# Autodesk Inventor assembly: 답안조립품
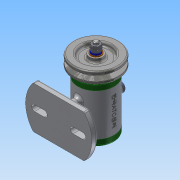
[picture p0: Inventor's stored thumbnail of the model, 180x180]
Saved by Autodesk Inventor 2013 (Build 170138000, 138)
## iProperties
Created: 2017-12
Part Number: 답안조립품
Document SubType Name: Assembly
Designer: Administrator
Author: Administrator
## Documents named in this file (14)
- C:\Users\Administrator\Desktop\471208V1011\답안조립품.iam
- C:\Users\Administrator\Desktop\471208V1011\본체.ipt
- C:\Users\Administrator\Desktop\471208V1011\V벨트풀리.ipt
- C:\Users\Administrator\Desktop\471208V1011\고무캡.ipt
- C:\Users\Administrator\Desktop\471208V1011\너트 M 8.ipt
- C:\Users\Administrator\Desktop\471208V1011\뒤커버.ipt
- C:\Users\Administrator\Desktop\471208V1011\베어링 15 x 32 x 9.ipt
- C:\Users\Administrator\Desktop\471208V1011\볼트 M4 x 12.ipt
- C:\Users\Administrator\Desktop\471208V1011\스프링와셔 8.ipt
- C:\Users\Administrator\Desktop\471208V1011\앞커버.ipt
- C:\Users\Administrator\Desktop\471208V1011\오일 실 15 25 7.ipt
- C:\Users\Administrator\Desktop\471208V1011\와셔 8x17.ipt
- C:\Users\Administrator\Desktop\471208V1011\축.ipt
- C:\Users\Administrator\Desktop\471208V1011\키 3 x 3 x 12.ipt
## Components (2 placed, 2 different names)
1. V벨트풀리:1
2. 고무캡:1
